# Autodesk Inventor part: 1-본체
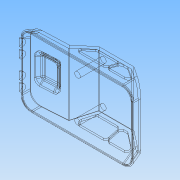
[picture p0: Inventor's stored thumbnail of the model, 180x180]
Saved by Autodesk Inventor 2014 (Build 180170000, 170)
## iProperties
Created: 2015-05
Part Number: 1-본체
Material: Generic
Document SubType Name: Modeling
Designer: Administrator
Density: 1 g/cm^3
Appearance: Default
Author: Administrator
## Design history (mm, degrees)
sketch "스케치1"
  geometry: L1 (0, 0)-(122, 0); L2 (122, 0)-(119.321, 10); L3 (119.321, 10)-(92, 30); L4 (42, 10.089)-(2.144, 8); L5 (2.144, 8)-(0, 0); L6 (92, 30)-(54.442, 30); L7 (54.442, 30)-(42, 10.089)
  constraints: 14 end point, 1 horizontal, 1 parallel
  dimensions: "d1" = 122 distance of L1.start L1.end; "d4" = 20 vertical distance of L3.end L2.end; "d5" = 30 horizontal distance of L3.end L1.end; "d7" = 8 vertical distance of L4.end L1.start; "d11" = 105 deg angle of L1 L5; "d53" = 30 horizontal distance of L3.end L1.end; "d59" = 105 deg angle of L1 L2; "d61" = 42 horizontal distance of L4.start L1.start; "d63" = 125 deg angle of L7 L4; "d64" = 3 deg angle of L1 L4
extrude "돌출1" new body sketch "스케치1" stored distance "d17" = 76; taper "d18" = 0 deg
sketch "스케치2"
  geometry: L1 (10, 38)-(30, 38) reference; L2 (0, 38)-(10, 38) reference; L3 (30, -38)-(10, -38) reference; L4 (10, -38)-(0, -38) reference; L5 (30, -38)-(30, 38) reference; L6 (0, -38)-(30, -29.962); L7 (0, 38)-(30, 38); L8 (30, -29.962)-(30, -38); L9 (0, -38)-(30, -38); L10 (0, 38)-(30, 29.962); L11 (30, 38)-(30, 29.962); 5 further points
  constraints: 12 end point, 2 collinear, 2 perpendicular, 2 point on line
  dimensions: "d20" = 15 deg angle of L3 L6; "d21" = 15 deg angle of L10 L1
extrude "돌출2" cut sketch "스케치2" stored distance "d22" = 76; taper "d23" = 0 deg
sketch "스케치3"
  geometry: L1 (11.441, 48.856)-(25.441, 48.856); L2 (28.441, 45.856)-(28.441, 25.856); L3 (25.441, 22.856)-(11.441, 22.856); L4 (8.441, 25.856)-(8.441, 45.856); L5 (-2.559, -2.144)-(-2.559, 73.856) reference; A1 r 3 centre (11.441, 45.856) between (11.441, 48.856) and (8.441, 45.856); A2 r 3 centre (11.441, 25.856) between (8.441, 25.856) and (11.441, 22.856); A3 r 3 centre (25.441, 25.856) between (25.441, 22.856) and (28.441, 25.856); A4 r 3 centre (25.441, 45.856) between (28.441, 45.856) and (25.441, 48.856); 5 further points
  constraints: 8 end point, 8 point on circle, 8 tangent, 6 point on line, 4 centre point, 3 equal radius, 2 midpoint, 2 parallel, 1 horizontal, 1 horizontal alignment, 1 perpendicular
  dimensions: "d24" = 20 distance of point (8.441, 48.856) point (28.441, 48.856); "d25" = 26 distance of point (8.441, 22.856) point (8.441, 48.856); "d27" = 3 radius of A1; "d51" = 11 distance from line of point (8.441, 35.856) L5
extrude "돌출3" join sketch "스케치3" distance "d28" = 5; taper "d29" = 0 deg
fillet "모깎기1" dims "d30" = 3
fillet "모깎기2" dims "d50" = 12
feature "쉘1" dims "d31" = 2
node "작업 평면1"
sketch "스케치5"
  geometry: A1 r 4 centre (0, 21) between (0, 25) and (0, 17); A2 r 4 centre (0, 10) between (0, 14) and (0, 6); A3 r 4 centre (0, -10) between (0, -6) and (0, -14); A4 r 4 centre (0, -21) between (0, -17) and (0, -25); 5 further points
  constraints: 8 point on circle, 4 centre point, 3 equal radius, 13 other
  dimensions: "d36" = 4 radius of A1; "d37" = 20 distance of A3.centre A2.centre; "d38" = 11 distance of A1.centre A2.centre; "d39" = 11 distance of A4.centre A3.centre; "d40" = 10 distance of point (0, 0) A2.centre
extrude "돌출5" join sketch "스케치5" stored distance "d41" = 1; taper "d42" = 0 deg
sketch "스케치6"
  geometry: L1 (56.332, 23.59)-(50.708, 14.59); L2 (53.253, 10)-(78.84, 10); L3 (81.84, 13)-(81.84, 22); L4 (78.84, 25)-(58.876, 25); L5 (82.856, 22)-(82.856, 13); L6 (85.856, 10)-(101.679, 10); L7 (103.451, 15.421)-(90.365, 25); L8 (90.365, 25)-(85.856, 25); L9 (42, 10.089)-(54.442, 30) reference; L10 (92, 30)-(104.901, 20.556) reference; L11 (54.442, 30)-(92, 30) reference; A1 r 3 centre (53.253, 13) between (50.708, 14.59) and (53.253, 10); A2 r 3 centre (58.876, 22) between (58.876, 25) and (56.332, 23.59); A3 r 3 centre (78.84, 22) between (81.84, 22) and (78.84, 25); A4 r 3 centre (78.84, 13) between (78.84, 10) and (81.84, 13); A5 r 3 centre (101.679, 13) between (101.679, 10) and (103.451, 15.421); A6 r 3 centre (85.856, 22) between (85.856, 25) and (82.856, 22); A7 r 3 centre (85.856, 13) between (82.856, 13) and (85.856, 10); 5 further points
  constraints: 16 end point, 14 point on circle, 14 tangent, 8 point on line, 7 centre point, 4 equal radius, 3 parallel, 2 collinear, 2 horizontal, 2 perpendicular, 1 vertical
  dimensions: "d43" = 34 distance of point (47.84, 10) point (81.84, 10); "d55" = 3 radius of A1; "d65" = 5 distance between parallel lines of L4 L11; "d66" = 5 distance between parallel lines of L10 L7; "d67" = 5 distance between parallel lines of L1 L9; "d68" = 3 radius of A6; "d69" = 15 distance between parallel lines of L2 L4; "d70" = 3 radius of A7; "d71" = 28 distance of point (110.856, 10) point (82.856, 10)
extrude "돌출6" cut sketch "스케치6" stored distance "d72" = 0; taper "d73" = 0 deg
sketch "스케치4"
  geometry: L1 (108.338, -11.73)-(108.338, -64.27) reference; L2 (98.679, -73.929)-(0.139, -73.929) reference; L3 (-9.521, -64.27)-(-9.521, -11.73) reference; L4 (0.139, -2.071)-(98.679, -2.071) reference; L5 (109.338, -11.73)-(109.338, -64.27); L6 (98.679, -74.929)-(0.139, -74.929); L7 (-10.521, -64.27)-(-10.521, -11.73); L8 (0.139, -1.071)-(98.679, -1.071); 4 further points; 4 other entities
  constraints: 8 end point, 7 parallel, 16 other
  dimensions: "d74" = 1 distance between parallel lines of L4 L8
extrude "돌출4" join sketch "스케치4" distance "d33" = 1; taper "d34" = 0 deg
sketch "스케치7"
  geometry: L1 (122, 0)-(110.409, 0) reference; L2 (11.591, 0)-(110.409, 0) reference; L3 (105.508, 0)-(101.938, 20.246); L4 (110.409, 0)-(110.409, 20.198); L5 (115.71, 10.165)-(113.917, 0); L6 (91.346, 28)-(105.555, 17.599) reference; L7 (105.555, 17.599)-(117.571, 8.802) reference; L8 (122, 0)-(119.321, 10) reference; 1 further point
  constraints: 6 end point, 4 point on line, 1 coincident, 1 perpendicular
  dimensions: "d91" = 10 deg angle of L4 L3; "d92" = 20 deg angle of L5 L3
extrude "돌출7" join sketch "스케치7" stored distance "d77" = 1; taper "d78" = 5 deg
sketch "스케치8"
  geometry: C1 r 5 at (0, 0) reference; C2 r 3 at (0, 0); 1 further point
  constraints: 1 centre point, 1 coincident
  dimensions: "d79" = 6 diameter of C2
extrude "돌출8" join sketch "스케치8" stored distance "d80" = 1; taper "d81" = 2 deg
sketch "스케치9"
  geometry: C1 r 3 at (49.409, -16); C2 r 3 at (49.409, -60); C3 r 3.035 at (89.409, -38) reference; 1 further point
  constraints: 2 centre point, 1 equal radius, 1 vertical alignment
  dimensions: "d84" = 44 distance of C2.centre C1.centre; "d85" = 6 diameter of C1; "d86" = 22 vertical distance of point (-11.591, -38) C1.centre; "d87" = 40 horizontal distance of C3.centre C1.centre
extrude "돌출9" join sketch "스케치9" stored distance "d88" = 1; taper "d89" = 0 deg
node "솔리드1"
other parameters: "d35" = -2
